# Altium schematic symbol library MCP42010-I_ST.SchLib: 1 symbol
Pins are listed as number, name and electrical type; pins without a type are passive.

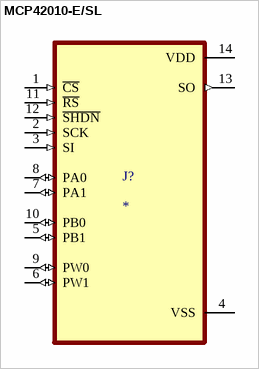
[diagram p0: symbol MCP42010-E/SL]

## MCP42010-E/SL
designator J?
DIGITAL POT, 256 STEPS, SPI, 10KOHMS, DUAL CHANNEL ¦ Microchip Technology Inc. MCP42010-E/SL
footprint SOP65P640X120-14N
pins: 1 ~{CS} (in), 2 SCK (in), 3 SI (in), 4 VSS (power), 5 PB1 (io), 6 PW1 (io), 7 PA1 (io), 8 PA0 (io), 9 PW0 (io), 10 PB0 (io), 11 ~{RS} (in), 12 ~{SHDN} (in), 13 SO (out), 14 VDD (power)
